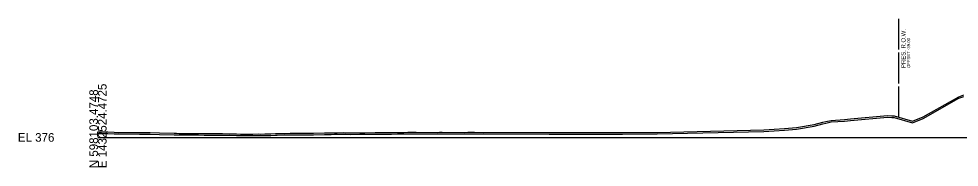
# Model space of a CAD drawing. Extents: x -26 to 2203, y -10 to 12201.
# Drawn here: x -25.7 to 279.6, y 1490.3 to 1538.6 of the extents above; entities that cross this region are included whole.
import ezdxf

# ---------------------------------------------------------------- set-up
doc = ezdxf.new("R2010")
doc.units = 0
for name, color, linetype in [('DESIGN - SHEET - Light Grid', 7, 'Continuous'), ('SURVEY - GROUND - Bottom of Topsoil Layer', 7, 'Continuous'), ('SURVEY - GROUND - Top of Ground', 7, 'Continuous'), ('SURVEY - PROPERTY - ROW Lines', 7, 'Continuous'), ('SURVEY - PROPERTY - ROW Lines Text', 7, 'Continuous')]:
    doc.layers.add(name, color=color, linetype=linetype)

msp = doc.modelspace()

# ---------------------------------------------------------------- linework, layer by layer
at = {"layer": 'DESIGN - SHEET - Light Grid'}
msp.add_line((0, 1500), (300, 1500), dxfattribs=at)
at = {"layer": 'SURVEY - GROUND - Bottom of Topsoil Layer'}
for p, q in [((267.85, 1506.17), (279.46, 1512.73)), ((279.46, 1512.73), (281.06, 1513.31)), ((236.24, 1504.67), (238, 1505.02)), ((238, 1505.02), (242.3, 1505.29)), ((242.3, 1505.29), (244.27, 1505.5)), ((244.27, 1505.5), (256.27, 1506.62)), ((256.27, 1506.62), (257.73, 1506.5)), ((257.73, 1506.5), (258.51, 1506.52)), ((258.51, 1506.52), (264.44, 1504.74)), ((264.44, 1504.74), (267.85, 1506.17)), ((181.54, 1501.15), (216.17, 1501.95)), ((216.17, 1501.95), (222.85, 1502.39)), ((222.85, 1502.39), (226.73, 1502.68)), ((226.73, 1502.68), (232.5, 1503.71)), ((232.5, 1503.71), (235.29, 1504.42)), ((235.29, 1504.42), (236.24, 1504.67)), ((0, 1501.31), (1.22, 1501.29)), ((1.22, 1501.29), (3.24, 1501.27)), ((3.24, 1501.27), (5.21, 1501.18)), ((5.21, 1501.18), (6.76, 1501.14)), ((6.76, 1501.14), (13.53, 1501.09)), ((13.53, 1501.09), (15.81, 1501.07)), ((15.81, 1501.07), (16.9, 1501.06)), ((16.9, 1501.06), (20.01, 1500.96)), ((20.01, 1500.96), (24.75, 1500.85)), ((24.75, 1500.85), (25.45, 1500.84)), ((25.45, 1500.84), (26.41, 1500.81)), ((26.41, 1500.81), (27.78, 1500.81)), ((27.78, 1500.81), (29.9, 1500.82)), ((29.9, 1500.82), (32.59, 1500.81)), ((32.59, 1500.81), (34.47, 1500.72)), ((34.47, 1500.72), (35.06, 1500.72)), ((35.06, 1500.72), (37.02, 1500.73)), ((37.02, 1500.73), (38.47, 1500.76)), ((38.47, 1500.76), (39.67, 1500.76)), ((39.67, 1500.76), (40.43, 1500.75)), ((40.43, 1500.75), (42.59, 1500.71)), ((42.59, 1500.71), (44.97, 1500.61)), ((44.97, 1500.61), (46.31, 1500.59)), ((46.31, 1500.59), (47.62, 1500.58)), ((47.62, 1500.58), (50.27, 1500.6)), ((50.27, 1500.6), (52.19, 1500.61)), ((52.19, 1500.61), (52.92, 1500.6)), ((52.92, 1500.6), (54.15, 1500.61)), ((54.15, 1500.61), (55.57, 1500.64)), ((55.57, 1500.64), (56.11, 1500.67)), ((56.11, 1500.67), (57.64, 1500.72)), ((57.64, 1500.72), (58.22, 1500.75)), ((58.22, 1500.75), (60.53, 1500.81)), ((60.53, 1500.81), (62.4, 1500.84)), ((62.4, 1500.84), (65.33, 1500.85)), ((65.33, 1500.85), (67.31, 1500.86)), ((67.31, 1500.86), (68.82, 1500.86)), ((68.82, 1500.86), (70.02, 1500.84)), ((70.02, 1500.84), (73.53, 1500.97)), ((73.53, 1500.97), (74.13, 1500.97)), ((74.13, 1500.97), (75.71, 1500.99)), ((75.71, 1500.99), (76.78, 1501.03)), ((76.78, 1501.03), (77.67, 1501.01)), ((77.67, 1501.01), (79.63, 1501.05)), ((79.63, 1501.05), (80.22, 1501.03)), ((80.22, 1501.03), (82.08, 1500.98)), ((82.08, 1500.98), (84.99, 1501.04)), ((84.99, 1501.04), (86.64, 1501.04)), ((86.64, 1501.04), (90.03, 1501.08)), ((90.03, 1501.08), (95.33, 1501.06)), ((95.33, 1501.06), (97.28, 1501.11)), ((97.28, 1501.11), (97.98, 1501.13)), ((97.98, 1501.13), (99.24, 1501.15)), ((99.24, 1501.15), (100.63, 1501.17)), ((100.63, 1501.17), (101.2, 1501.17)), ((101.2, 1501.17), (102.8, 1501.16)), ((102.8, 1501.16), (103.28, 1501.16)), ((103.28, 1501.16), (110.33, 1501.15)), ((110.33, 1501.15), (110.92, 1501.16)), ((110.92, 1501.16), (111.24, 1501.16)), ((111.24, 1501.16), (111.73, 1501.16)), ((111.73, 1501.16), (118.84, 1501.14)), ((118.84, 1501.14), (120.11, 1501.18)), ((120.11, 1501.18), (121.84, 1501.17)), ((121.84, 1501.17), (122.28, 1501.18)), ((122.28, 1501.18), (125.11, 1501.15)), ((125.11, 1501.15), (146.52, 1501.08)), ((146.52, 1501.08), (170.27, 1501.07)), ((170.27, 1501.07), (181.54, 1501.15))]:
    msp.add_line(p, q, dxfattribs=at)
at = {"layer": 'SURVEY - GROUND - Top of Ground'}
for p, q in [((267.85, 1506.67), (279.46, 1513.23)), ((279.46, 1513.23), (281.06, 1513.81)), ((235.29, 1504.92), (236.24, 1505.17)), ((236.24, 1505.17), (238, 1505.52)), ((238, 1505.52), (242.3, 1505.79)), ((242.3, 1505.79), (244.27, 1506)), ((244.27, 1506), (256.27, 1507.12)), ((256.27, 1507.12), (257.73, 1507)), ((257.73, 1507), (258.51, 1507.02)), ((258.51, 1507.02), (264.44, 1505.24)), ((264.44, 1505.24), (267.85, 1506.67)), ((181.54, 1501.65), (216.17, 1502.45)), ((216.17, 1502.45), (222.85, 1502.89)), ((222.85, 1502.89), (226.73, 1503.18)), ((226.73, 1503.18), (232.5, 1504.21)), ((232.5, 1504.21), (235.29, 1504.92)), ((0, 1501.81), (1.22, 1501.79)), ((1.22, 1501.79), (3.24, 1501.77)), ((3.24, 1501.77), (5.21, 1501.68)), ((5.21, 1501.68), (6.76, 1501.64)), ((6.76, 1501.64), (13.53, 1501.59)), ((13.53, 1501.59), (15.81, 1501.57)), ((15.81, 1501.57), (16.9, 1501.56)), ((16.9, 1501.56), (20.01, 1501.46)), ((20.01, 1501.46), (24.75, 1501.35)), ((24.75, 1501.35), (25.45, 1501.34)), ((25.45, 1501.34), (26.41, 1501.31)), ((26.41, 1501.31), (27.78, 1501.31)), ((27.78, 1501.31), (29.9, 1501.32)), ((29.9, 1501.32), (32.59, 1501.31)), ((32.59, 1501.31), (34.47, 1501.22)), ((34.47, 1501.22), (35.06, 1501.22)), ((35.06, 1501.22), (37.02, 1501.23)), ((37.02, 1501.23), (38.47, 1501.26)), ((38.47, 1501.26), (39.67, 1501.26)), ((39.67, 1501.26), (40.43, 1501.25)), ((40.43, 1501.25), (42.59, 1501.21)), ((42.59, 1501.21), (44.97, 1501.11)), ((44.97, 1501.11), (46.31, 1501.09)), ((46.31, 1501.09), (47.62, 1501.08)), ((47.62, 1501.08), (50.27, 1501.1)), ((50.27, 1501.1), (52.19, 1501.11)), ((52.19, 1501.11), (52.92, 1501.1)), ((52.92, 1501.1), (54.15, 1501.11)), ((54.15, 1501.11), (55.57, 1501.14)), ((55.57, 1501.14), (56.11, 1501.17)), ((56.11, 1501.17), (57.64, 1501.22)), ((57.64, 1501.22), (58.22, 1501.25)), ((58.22, 1501.25), (60.53, 1501.31)), ((60.53, 1501.31), (62.4, 1501.34)), ((62.4, 1501.34), (65.33, 1501.35)), ((65.33, 1501.35), (67.31, 1501.36)), ((67.31, 1501.36), (68.82, 1501.36)), ((68.82, 1501.36), (70.02, 1501.34)), ((70.02, 1501.34), (73.53, 1501.47)), ((73.53, 1501.47), (74.13, 1501.47)), ((74.13, 1501.47), (75.71, 1501.49)), ((75.71, 1501.49), (76.78, 1501.53)), ((76.78, 1501.53), (77.67, 1501.51)), ((77.67, 1501.51), (79.63, 1501.55)), ((79.63, 1501.55), (80.22, 1501.53)), ((80.22, 1501.53), (82.08, 1501.48)), ((82.08, 1501.48), (84.99, 1501.54)), ((84.99, 1501.54), (86.64, 1501.54)), ((86.64, 1501.54), (90.03, 1501.58)), ((90.03, 1501.58), (95.33, 1501.56)), ((95.33, 1501.56), (97.28, 1501.61)), ((97.28, 1501.61), (97.98, 1501.63)), ((97.98, 1501.63), (99.24, 1501.65)), ((99.24, 1501.65), (100.63, 1501.67)), ((100.63, 1501.67), (101.2, 1501.67)), ((101.2, 1501.67), (102.8, 1501.66)), ((102.8, 1501.66), (103.28, 1501.66)), ((103.28, 1501.66), (110.33, 1501.65)), ((110.33, 1501.65), (110.92, 1501.66)), ((110.92, 1501.66), (111.24, 1501.66)), ((111.24, 1501.66), (111.73, 1501.66)), ((111.73, 1501.66), (118.84, 1501.64)), ((118.84, 1501.64), (120.11, 1501.68)), ((120.11, 1501.68), (121.84, 1501.67)), ((121.84, 1501.67), (122.28, 1501.68)), ((122.28, 1501.68), (125.11, 1501.65)), ((125.11, 1501.65), (146.52, 1501.58)), ((146.52, 1501.58), (170.27, 1501.57)), ((170.27, 1501.57), (181.54, 1501.65))]:
    msp.add_line(p, q, dxfattribs=at)
at = {"layer": 'SURVEY - PROPERTY - ROW Lines'}
for p, q in [((260, 1528.57), (260, 1538.57)), ((260, 1517.57), (260, 1527.57)), ((260, 1506.57), (260, 1516.57))]:
    msp.add_line(p, q, dxfattribs=at)

# ---------------------------------------------------------------- texts
at = {"layer": 'DESIGN - SHEET - Light Grid'}
for s, p in [('E 1432524.4725', (2.8, 1490)), ('N 598103.4748', (0, 1490))]:
    msp.add_text(s, height=2.8, rotation=90, dxfattribs=at).set_placement(p)
msp.add_text('EL 376', height=2.8, dxfattribs=at).set_placement((-26, 1498.6))
at = {"layer": 'SURVEY - PROPERTY - ROW Lines Text'}
for s, height, p in [('PRES. R.O.W.', 1.4, (262.15, 1522.57)), ('OFFSET -39.00', 1, (263.65, 1522.57))]:
    msp.add_text(s, height=height, rotation=90, dxfattribs=at).set_placement(p)

doc.saveas('drawing.dxf')
